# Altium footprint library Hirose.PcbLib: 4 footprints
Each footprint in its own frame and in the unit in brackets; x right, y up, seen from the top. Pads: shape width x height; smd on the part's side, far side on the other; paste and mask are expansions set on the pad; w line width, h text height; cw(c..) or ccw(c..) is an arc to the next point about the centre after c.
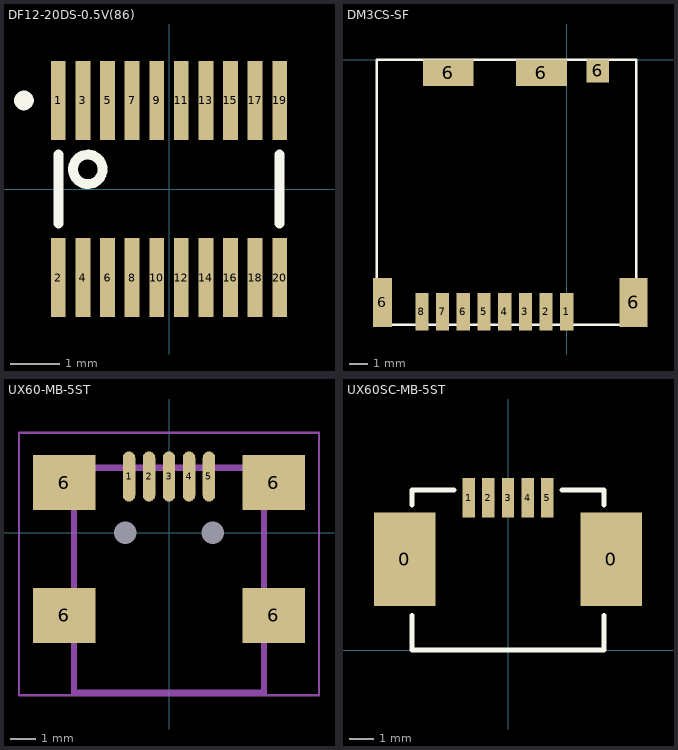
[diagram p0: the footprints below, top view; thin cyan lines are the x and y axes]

## DF12-20DS-0.5V(86) [mm]
height 2.7
pads (20):
  rect 0.3x1.6 smd: 1(-2.25,1.8) 2(-2.25,-1.8) 3(-1.75,1.8) 4(-1.75,-1.8) 5(-1.25,1.8) 6(-1.25,-1.8) 7(-0.75,1.8) 8(-0.75,-1.8) 9(-0.25,1.8) 10(-0.25,-1.8) 11(0.25,1.8) 12(0.25,-1.8) 13(0.75,1.8) 14(0.75,-1.8) 15(1.25,1.8) 16(1.25,-1.8) 17(1.75,1.8) 18(1.75,-1.8) 19(2.25,1.8) 20(2.25,-1.8)
Top Overlay:
  circle w0.2: c-2.95,1.8 r0.1
  circle w0.2: c-1.65,0.4 r0.3
  lines w0.2: -2.25,-0.7 -2.25,0.7 ; 2.25,-0.7 2.25,0.7
3D body: height 2.2, standoff 0, extent -2.8,-1.2 2.8,1.2
3D body: height 0.75, standoff 0, extent -3.6,-1.8 3.6,1.8

## DM3CS-SF [mm] "Micro-SD connector, hinged"
height 1.85
pads (13):
  rect 0.7x2 smd: 1(0,-13.4) 2(-1.1,-13.4) 3(-2.2,-13.4) 4(-3.3,-13.4) 5(-4.4,-13.4) 6(-5.5,-13.4) 7(-6.6,-13.4) 8(-7.7,-13.4)
  rect 1x2.6 smd: 6(-9.8,-12.9)
  rect 2.7x1.4 smd: 6(-6.3,-0.7) 6(-1.35,-0.7)
  rect 1.2x1.2 smd: 6(1.65,-0.6)
  rect 1.5x2.6 smd: 6(3.55,-12.9)
Top Overlay:
  lines w0.127: -10.1,-14.1 -10.1,0 3.7,0 3.7,-14.1 -10.1,-14.1
3D body: height 1.85, standoff 0, extent -10.1,-14.1 3.7,0

## UX60-MB-5ST [mm] "USB Mini-AB Receptacle"
height 4
pads (11):
  round 0 hole 0.9 unplated: 0(-1.75,0) 0(1.75,0)
  oval 0.5x2 smd mask+0.051: 1(-1.6,2.25) 2(-0.8,2.25) 3(0,2.25) 4(0.8,2.25) 5(1.6,2.25)
  rect 2.5x2.2 smd: 6(-4.2,-3.3) 6(-4.2,2) 6(4.2,-3.3) 6(4.2,2)
Mechanical 13:
  lines w0.254: -3.8,-6.4 -3.8,2.6 3.8,2.6 3.8,-6.4 -3.8,-6.4
Mechanical 15:
  lines w0.1: -6,-6.5 6,-6.5 6,4 -6,4 -6,-6.5
3D body: height 3.95, standoff -0.5, extent -5.05,-6.4 5.05,2.6

## UX60SC-MB-5ST [mm] "USB Mini-B receptacle"
height 3.95
pads (7):
  rect 2.5x3.8 smd: 0(-4.2,3.7) 0(4.2,3.7)
  rect 0.5x1.6 smd: 1(-1.6,6.2) 2(-0.8,6.2) 3(0,6.2) 4(0.8,6.2) 5(1.6,6.2)
Top Overlay:
  lines w0.203: -3.9,1.4 -3.9,0 3.9,0 3.9,1.4 ; -3.9,5.9 -3.9,6.5 -2.2,6.5 ; 2.2,6.5 3.9,6.5 3.9,5.9
3D body: height 3.95, standoff 0, extent -3.9,0 3.9,6.5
